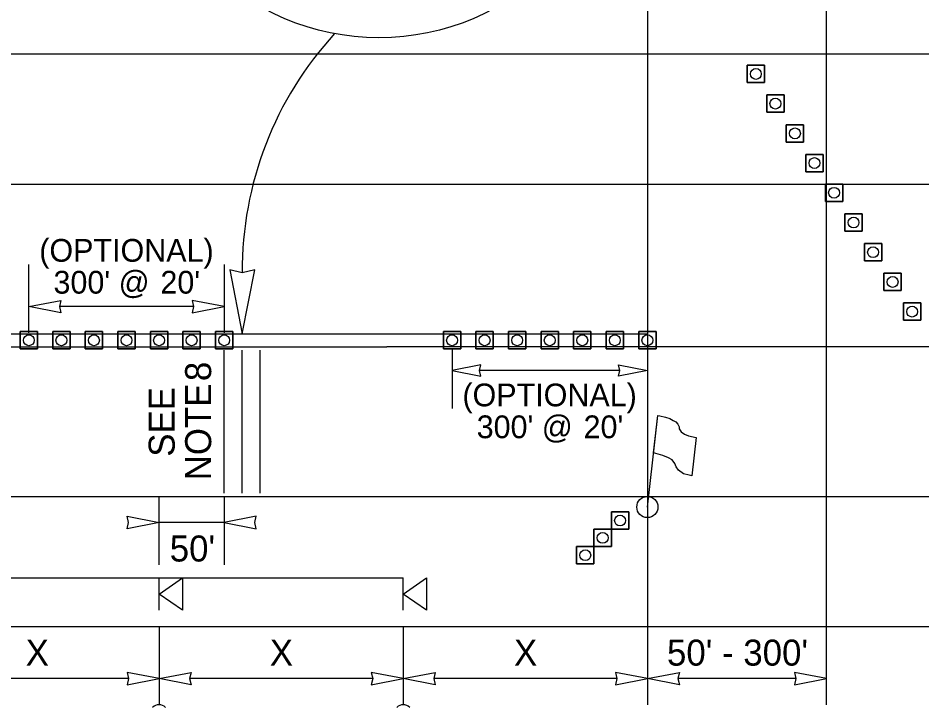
# Model space of a CAD drawing. Extents: x 99999.1 to 100095.7, y 99995 to 100010.7.
# Drawn here: x 100002.344 to 100005.12, y 100005.488 to 100007.603 of the extents above; entities that cross this region are included whole.
import ezdxf

# ---------------------------------------------------------------- set-up
doc = ezdxf.new("R2010")
doc.units = 0
for name, color, linetype in [('RD_ED_ShoulderPavedEdge', 7, 'Continuous'), ('RD_MK_LineDblYellowCenter', 7, 'Continuous'), ('RD_MK_LineEdgeWhite', 7, 'Continuous'), ('RD_MK_LineNoPass', 7, 'Continuous'), ('RD_MK_LineSkipCenter', 7, 'Continuous'), ('TR_SN_ConstructionSigns', 7, 'Continuous'), ('TR_WZ_FlaggingStation', 7, 'Continuous'), ('TR_WZ_PortableSignMountBlk-Org', 7, 'Continuous'), ('TR_WZ_TrafficCone', 7, 'Continuous'), ('TR_WZ_WorkZoneDetails', 7, 'Continuous'), ('TR_WZ_WorkZoneTextCurrent', 7, 'Continuous')]:
    doc.layers.add(name, color=color, linetype=linetype)

msp = doc.modelspace()

# ---------------------------------------------------------------- linework, layer by layer
at = {"layer": 'RD_ED_ShoulderPavedEdge'}
for p, q in [((100000.1076, 100007.4923), (100015.6424, 100007.4923)), ((100000.1076, 100005.7323), (100015.6424, 100005.7323))]:
    msp.add_line(p, q, dxfattribs=at)
at = {"layer": 'RD_MK_LineDblYellowCenter'}
for p, q in [((100000.1282, 100006.6323), (100003.4767, 100006.6323)), ((100000.0869, 100006.5923), (100003.4767, 100006.5923))]:
    msp.add_line(p, q, dxfattribs=at)
at = {"layer": 'RD_MK_LineEdgeWhite'}
for p, q in [((100000.1076, 100007.0923), (100015.6424, 100007.0923)), ((100000.1076, 100006.1323), (100015.6424, 100006.1323))]:
    msp.add_line(p, q, dxfattribs=at)
at = {"layer": 'RD_MK_LineNoPass'}
msp.add_line((100003.4767, 100006.6323), (100004.2767, 100006.6323), dxfattribs=at)
at = {"layer": 'RD_MK_LineSkipCenter'}
msp.add_lwpolyline([(100011.15, 100006.5923), (100003.4767, 100006.5923)], dxfattribs=at)
at = {"layer": 'TR_SN_ConstructionSigns'}
for centre in [(100002.7767, 100005.4642), (100003.5267, 100005.4642)]:
    msp.add_arc(centre, 0.0281, 45, 135, dxfattribs=at)
at = {"layer": 'TR_WZ_FlaggingStation'}
for p, q in [((100004.2767, 100006.0998), (100004.3087, 100006.3808)), ((100004.2957, 100006.2667), (100004.3087, 100006.3811)), ((100004.4267, 100006.3133), (100004.4134, 100006.1961)), ((100004.2957, 100006.2667), (100004.2957, 100006.2667))]:
    msp.add_line(p, q, dxfattribs=at)
for points in [[(100004.3087, 100006.3811), (100004.3145, 100006.3798), (100004.3323, 100006.3764), (100004.3461, 100006.3722), (100004.3558, 100006.3661), (100004.3643, 100006.3614), (100004.37, 100006.3546), (100004.3743, 100006.3467), (100004.3748, 100006.3405), (100004.3802, 100006.3313), (100004.391, 100006.3239), (100004.4034, 100006.3187), (100004.4267, 100006.3133)], [(100004.4134, 100006.1961), (100004.4052, 100006.1975), (100004.3876, 100006.2021), (100004.3719, 100006.2126), (100004.3654, 100006.2232), (100004.3615, 100006.2335), (100004.3524, 100006.2444), (100004.3414, 100006.2506), (100004.3241, 100006.2577), (100004.2957, 100006.2667)]]:
    msp.add_lwpolyline(points, dxfattribs=at)
msp.add_circle((100004.2767, 100006.0998), 0.0325, dxfattribs=at)
at = {"layer": 'TR_WZ_PortableSignMountBlk-Org'}
for p, q in [((100002.7767, 100005.7824), (100002.7767, 100005.8824)), ((100003.5267, 100005.7824), (100003.5267, 100005.8824))]:
    msp.add_line(p, q, dxfattribs=at)
for points in [[(100002.7767, 100005.8323), (100002.8485, 100005.8824), (100002.8485, 100005.7824)], [(100003.5267, 100005.8323), (100003.5985, 100005.8824), (100003.5985, 100005.7824)]]:
    msp.add_lwpolyline(points, close=True, dxfattribs=at)
at = {"layer": 'TR_WZ_TrafficCone'}
for points in [[(100004.6367, 100007.4577), (100004.5834, 100007.4577), (100004.5834, 100007.4043), (100004.6367, 100007.4043), (100004.6367, 100007.4577)], [(100004.6367, 100007.4043), (100004.5834, 100007.4043), (100004.5834, 100007.4577), (100004.6367, 100007.4577), (100004.6367, 100007.4043)], [(100004.6967, 100007.3663), (100004.6434, 100007.3663), (100004.6434, 100007.313), (100004.6967, 100007.313), (100004.6967, 100007.3663)], [(100004.6967, 100007.313), (100004.6434, 100007.313), (100004.6434, 100007.3663), (100004.6967, 100007.3663), (100004.6967, 100007.313)], [(100004.7567, 100007.275), (100004.7034, 100007.275), (100004.7034, 100007.2217), (100004.7567, 100007.2217), (100004.7567, 100007.275)], [(100004.7567, 100007.2217), (100004.7034, 100007.2217), (100004.7034, 100007.275), (100004.7567, 100007.275), (100004.7567, 100007.2217)], [(100004.8167, 100007.1837), (100004.7634, 100007.1837), (100004.7634, 100007.1303), (100004.8167, 100007.1303), (100004.8167, 100007.1837)], [(100004.8167, 100007.1303), (100004.7634, 100007.1303), (100004.7634, 100007.1837), (100004.8167, 100007.1837), (100004.8167, 100007.1303)], [(100004.8234, 100007.0923), (100004.8767, 100007.0923), (100004.8767, 100007.039), (100004.8234, 100007.039), (100004.8234, 100007.0923)], [(100004.8234, 100007.039), (100004.8767, 100007.039), (100004.8767, 100007.0923), (100004.8234, 100007.0923), (100004.8234, 100007.039)], [(100004.8834, 100007.001), (100004.9367, 100007.001), (100004.9367, 100006.9477), (100004.8834, 100006.9477), (100004.8834, 100007.001)], [(100004.8834, 100006.9477), (100004.9367, 100006.9477), (100004.9367, 100007.001), (100004.8834, 100007.001), (100004.8834, 100006.9477)], [(100004.9434, 100006.9097), (100004.9967, 100006.9097), (100004.9967, 100006.8563), (100004.9434, 100006.8563), (100004.9434, 100006.9097)], [(100004.9434, 100006.8563), (100004.9967, 100006.8563), (100004.9967, 100006.9097), (100004.9434, 100006.9097), (100004.9434, 100006.8563)], [(100005.0034, 100006.8183), (100005.0567, 100006.8183), (100005.0567, 100006.765), (100005.0034, 100006.765), (100005.0034, 100006.8183)], [(100005.0034, 100006.765), (100005.0567, 100006.765), (100005.0567, 100006.8183), (100005.0034, 100006.8183), (100005.0034, 100006.765)], [(100005.0634, 100006.727), (100005.1167, 100006.727), (100005.1167, 100006.6737), (100005.0634, 100006.6737), (100005.0634, 100006.727)], [(100005.0634, 100006.6737), (100005.1167, 100006.6737), (100005.1167, 100006.727), (100005.0634, 100006.727), (100005.0634, 100006.6737)], [(100002.4033, 100006.639), (100002.35, 100006.639), (100002.35, 100006.5857), (100002.4033, 100006.5857), (100002.4033, 100006.639)], [(100002.4033, 100006.5857), (100002.35, 100006.5857), (100002.35, 100006.639), (100002.4033, 100006.639), (100002.4033, 100006.5857)], [(100002.5033, 100006.639), (100002.45, 100006.639), (100002.45, 100006.5857), (100002.5033, 100006.5857), (100002.5033, 100006.639)], [(100002.5033, 100006.5857), (100002.45, 100006.5857), (100002.45, 100006.639), (100002.5033, 100006.639), (100002.5033, 100006.5857)], [(100002.6033, 100006.639), (100002.55, 100006.639), (100002.55, 100006.5857), (100002.6033, 100006.5857), (100002.6033, 100006.639)], [(100002.6033, 100006.5857), (100002.55, 100006.5857), (100002.55, 100006.639), (100002.6033, 100006.639), (100002.6033, 100006.5857)], [(100002.7033, 100006.639), (100002.65, 100006.639), (100002.65, 100006.5857), (100002.7033, 100006.5857), (100002.7033, 100006.639)], [(100002.7033, 100006.5857), (100002.65, 100006.5857), (100002.65, 100006.639), (100002.7033, 100006.639), (100002.7033, 100006.5857)], [(100002.8033, 100006.639), (100002.75, 100006.639), (100002.75, 100006.5857), (100002.8033, 100006.5857), (100002.8033, 100006.639)], [(100002.8033, 100006.5857), (100002.75, 100006.5857), (100002.75, 100006.639), (100002.8033, 100006.639), (100002.8033, 100006.5857)], [(100002.9033, 100006.639), (100002.85, 100006.639), (100002.85, 100006.5857), (100002.9033, 100006.5857), (100002.9033, 100006.639)], [(100002.9033, 100006.5857), (100002.85, 100006.5857), (100002.85, 100006.639), (100002.9033, 100006.639), (100002.9033, 100006.5857)], [(100003.0033, 100006.639), (100002.95, 100006.639), (100002.95, 100006.5857), (100003.0033, 100006.5857), (100003.0033, 100006.639)], [(100003.0033, 100006.5857), (100002.95, 100006.5857), (100002.95, 100006.639), (100003.0033, 100006.639), (100003.0033, 100006.5857)], [(100003.7033, 100006.639), (100003.65, 100006.639), (100003.65, 100006.5857), (100003.7033, 100006.5857), (100003.7033, 100006.639)], [(100003.7033, 100006.5857), (100003.65, 100006.5857), (100003.65, 100006.639), (100003.7033, 100006.639), (100003.7033, 100006.5857)], [(100003.8033, 100006.639), (100003.75, 100006.639), (100003.75, 100006.5857), (100003.8033, 100006.5857), (100003.8033, 100006.639)], [(100003.8033, 100006.5857), (100003.75, 100006.5857), (100003.75, 100006.639), (100003.8033, 100006.639), (100003.8033, 100006.5857)], [(100003.9033, 100006.639), (100003.85, 100006.639), (100003.85, 100006.5857), (100003.9033, 100006.5857), (100003.9033, 100006.639)], [(100003.9033, 100006.5857), (100003.85, 100006.5857), (100003.85, 100006.639), (100003.9033, 100006.639), (100003.9033, 100006.5857)], [(100004.0033, 100006.639), (100003.95, 100006.639), (100003.95, 100006.5857), (100004.0033, 100006.5857), (100004.0033, 100006.639)], [(100004.0033, 100006.5857), (100003.95, 100006.5857), (100003.95, 100006.639), (100004.0033, 100006.639), (100004.0033, 100006.5857)], [(100004.1033, 100006.639), (100004.05, 100006.639), (100004.05, 100006.5857), (100004.1033, 100006.5857), (100004.1033, 100006.639)], [(100004.1033, 100006.5857), (100004.05, 100006.5857), (100004.05, 100006.639), (100004.1033, 100006.639), (100004.1033, 100006.5857)], [(100004.2033, 100006.639), (100004.15, 100006.639), (100004.15, 100006.5857), (100004.2033, 100006.5857), (100004.2033, 100006.639)], [(100004.2033, 100006.5857), (100004.15, 100006.5857), (100004.15, 100006.639), (100004.2033, 100006.639), (100004.2033, 100006.5857)], [(100004.3033, 100006.639), (100004.25, 100006.639), (100004.25, 100006.5857), (100004.3033, 100006.5857), (100004.3033, 100006.639)], [(100004.3033, 100006.5857), (100004.25, 100006.5857), (100004.25, 100006.639), (100004.3033, 100006.639), (100004.3033, 100006.5857)], [(100004.166, 100006.085), (100004.2193, 100006.085), (100004.2193, 100006.0317), (100004.166, 100006.0317), (100004.166, 100006.085)], [(100004.166, 100006.0317), (100004.2193, 100006.0317), (100004.2193, 100006.085), (100004.166, 100006.085), (100004.166, 100006.0317)], [(100004.1127, 100006.0317), (100004.166, 100006.0317), (100004.166, 100005.9783), (100004.1127, 100005.9783), (100004.1127, 100006.0317)], [(100004.1127, 100005.9783), (100004.166, 100005.9783), (100004.166, 100006.0317), (100004.1127, 100006.0317), (100004.1127, 100005.9783)], [(100004.0593, 100005.9783), (100004.1127, 100005.9783), (100004.1127, 100005.925), (100004.0593, 100005.925), (100004.0593, 100005.9783)], [(100004.0593, 100005.925), (100004.1127, 100005.925), (100004.1127, 100005.9783), (100004.0593, 100005.9783), (100004.0593, 100005.925)]]:
    msp.add_lwpolyline(points, dxfattribs=at)
for centre in [(100004.61, 100007.431), (100004.67, 100007.3397), (100004.73, 100007.2483), (100004.79, 100007.157), (100004.85, 100007.0657), (100004.91, 100006.9743), (100004.97, 100006.883), (100005.03, 100006.7917), (100005.09, 100006.7003), (100002.3767, 100006.6123), (100002.4767, 100006.6123), (100002.5767, 100006.6123), (100002.6767, 100006.6123), (100002.7767, 100006.6123), (100002.8767, 100006.6123), (100002.9767, 100006.6123), (100003.6767, 100006.6123), (100003.7767, 100006.6123), (100003.8767, 100006.6123), (100003.9767, 100006.6123), (100004.0767, 100006.6123), (100004.1767, 100006.6123), (100004.2767, 100006.6123), (100004.1927, 100006.0583), (100004.1393, 100006.005), (100004.086, 100005.9517)]:
    msp.add_circle(centre, 0.0167, dxfattribs=at)
at = {"layer": 'TR_WZ_WorkZoneDetails'}
for p, q in [((100004.2767, 100008.9491), (100004.2767, 100005.4923)), ((100004.8267, 100005.4923), (100004.8267, 100007.7323)), ((100002.3767, 100006.6357), (100002.3767, 100006.8457)), ((100002.9767, 100006.8457), (100002.9767, 100006.6357)), ((100002.8829, 100006.7157), (100002.4704, 100006.7157)), ((100002.9767, 100006.1423), (100002.9767, 100006.5823)), ((100003.0323, 100006.1423), (100003.0323, 100006.5823)), ((100003.0872, 100006.1423), (100003.0872, 100006.5823)), ((100003.6767, 100006.5857), (100003.6767, 100006.4023)), ((100004.2767, 100006.5857), (100004.2767, 100006.4023)), ((100004.1923, 100006.5193), (100003.761, 100006.5193)), ((100002.7767, 100005.9223), (100002.7767, 100006.1323)), ((100002.9767, 100006.1323), (100002.9767, 100005.9223)), ((100002.9767, 100006.0523), (100002.7767, 100006.0523)), ((100000.5267, 100005.8824), (100003.5267, 100005.8824)), ((100002.7767, 100005.7323), (100002.7767, 100005.4923)), ((100003.5267, 100005.7323), (100003.5267, 100005.4923)), ((100002.6829, 100005.5723), (100002.1204, 100005.5723)), ((100003.4329, 100005.5723), (100002.8704, 100005.5723)), ((100004.1829, 100005.5723), (100003.6204, 100005.5723)), ((100004.7329, 100005.5723), (100004.3704, 100005.5723))]:
    msp.add_line(p, q, dxfattribs=at)
for points in [[(100003.0323, 100006.6323), (100003.0708, 100006.8289), (100003.0323, 100006.8198), (100002.9937, 100006.8289)], [(100002.3767, 100006.7157), (100002.4749, 100006.7349), (100002.4704, 100006.7157), (100002.4749, 100006.6964)], [(100002.9767, 100006.7157), (100002.8784, 100006.7349), (100002.8829, 100006.7157), (100002.8784, 100006.6964)], [(100003.6767, 100006.5193), (100003.7651, 100006.502), (100003.761, 100006.5193), (100003.7651, 100006.5367)], [(100004.2767, 100006.5193), (100004.1882, 100006.502), (100004.1923, 100006.5193), (100004.1882, 100006.5367)], [(100002.7767, 100006.0523), (100002.6784, 100006.0331), (100002.6829, 100006.0523), (100002.6784, 100006.0716)], [(100002.9767, 100006.0523), (100003.0749, 100006.0331), (100003.0704, 100006.0523), (100003.0749, 100006.0716)], [(100002.7767, 100005.5723), (100002.6784, 100005.5916), (100002.6829, 100005.5723), (100002.6784, 100005.5531)], [(100002.7767, 100005.5723), (100002.8749, 100005.5916), (100002.8704, 100005.5723), (100002.8749, 100005.5531)], [(100003.5267, 100005.5723), (100003.4284, 100005.5916), (100003.4329, 100005.5723), (100003.4284, 100005.5531)], [(100003.5267, 100005.5723), (100003.6249, 100005.5916), (100003.6204, 100005.5723), (100003.6249, 100005.5531)], [(100004.2767, 100005.5723), (100004.1784, 100005.5916), (100004.1829, 100005.5723), (100004.1784, 100005.5531)], [(100004.2767, 100005.5723), (100004.3749, 100005.5916), (100004.3704, 100005.5723), (100004.3749, 100005.5531)], [(100004.8267, 100005.5723), (100004.7284, 100005.5916), (100004.7329, 100005.5723), (100004.7284, 100005.5531)]]:
    msp.add_lwpolyline(points, close=True, dxfattribs=at)
msp.add_circle((100003.4522, 100008.2843), 0.742, dxfattribs=at)
msp.add_arc((100004.1081, 100006.8268), 1.0759, 137.408, 180.3733, dxfattribs=at)

# ---------------------------------------------------------------- texts
for s, p in [('8', (100002.9367, 100006.4868)), ('NOTE', (100002.9367, 100006.182)), ('SEE', (100002.8247, 100006.2544))]:
    msp.add_text(s, height=0.08, rotation=90, dxfattribs=at).set_placement(p)
at = {"layer": 'TR_WZ_WorkZoneTextCurrent'}
for s, height, p in [('(OPTIONAL)', 0.07, (100002.4087, 100006.8537)), ("300' @", 0.07, (100002.4524, 100006.7557)), ("20'", 0.07, (100002.7808, 100006.7557)), ('(OPTIONAL)', 0.07, (100003.7085, 100006.4093)), ("300' @", 0.07, (100003.7523, 100006.3113)), ("20'", 0.07, (100004.0807, 100006.3113)), ("50'", 0.08, (100002.8094, 100005.9323))]:
    msp.add_text(s, height=height, dxfattribs=at).set_placement(p)
for s, p in [('X', (100002.3669, 100005.6123)), ('X', (100003.1169, 100005.6123)), ('X', (100003.8669, 100005.6123)), ("50' - 300'", (100004.3369, 100005.6123))]:
    msp.add_text(s, height=0.08, rotation=360, dxfattribs=at).set_placement(p)

doc.saveas('drawing.dxf')
